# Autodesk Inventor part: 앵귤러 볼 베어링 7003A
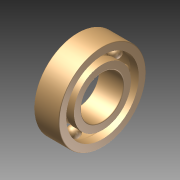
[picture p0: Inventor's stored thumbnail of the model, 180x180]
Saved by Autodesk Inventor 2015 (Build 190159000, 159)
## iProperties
Created: 2024-12
Part Number: 앵귤러 볼 베어링 7003A
Material: 일반
Document SubType Name: Modeling
Designer: 102566
Density: 1 g/cm^3
Appearance: 기본값
Author: 102566
Author: jhkim
Description: 앵귤러 콘택트 볼 베어링
Creation Date: 2024-11-28
Sending System: Autodesk Inventor 2025
Preprocessor: ST-DEVELOPER v20
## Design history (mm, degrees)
node "앵귤러 볼 베어링 7003A1"
body "Solid1"
node "Solid1_1"
node "Solid1_2"
node "Solid1_3"
node "Solid1_4"
node "Solid1_5"
node "Solid1_6"
node "Solid1_7"
node "Solid1_8"
node "Solid1_9"
node "Solid1_10"
node "기준1"
node "기준2"
node "기준3"
node "기준4"
node "기준5"
node "기준6"
node "기준7"
node "기준8"
node "기준9"
node "기준10"
node "기준11"
